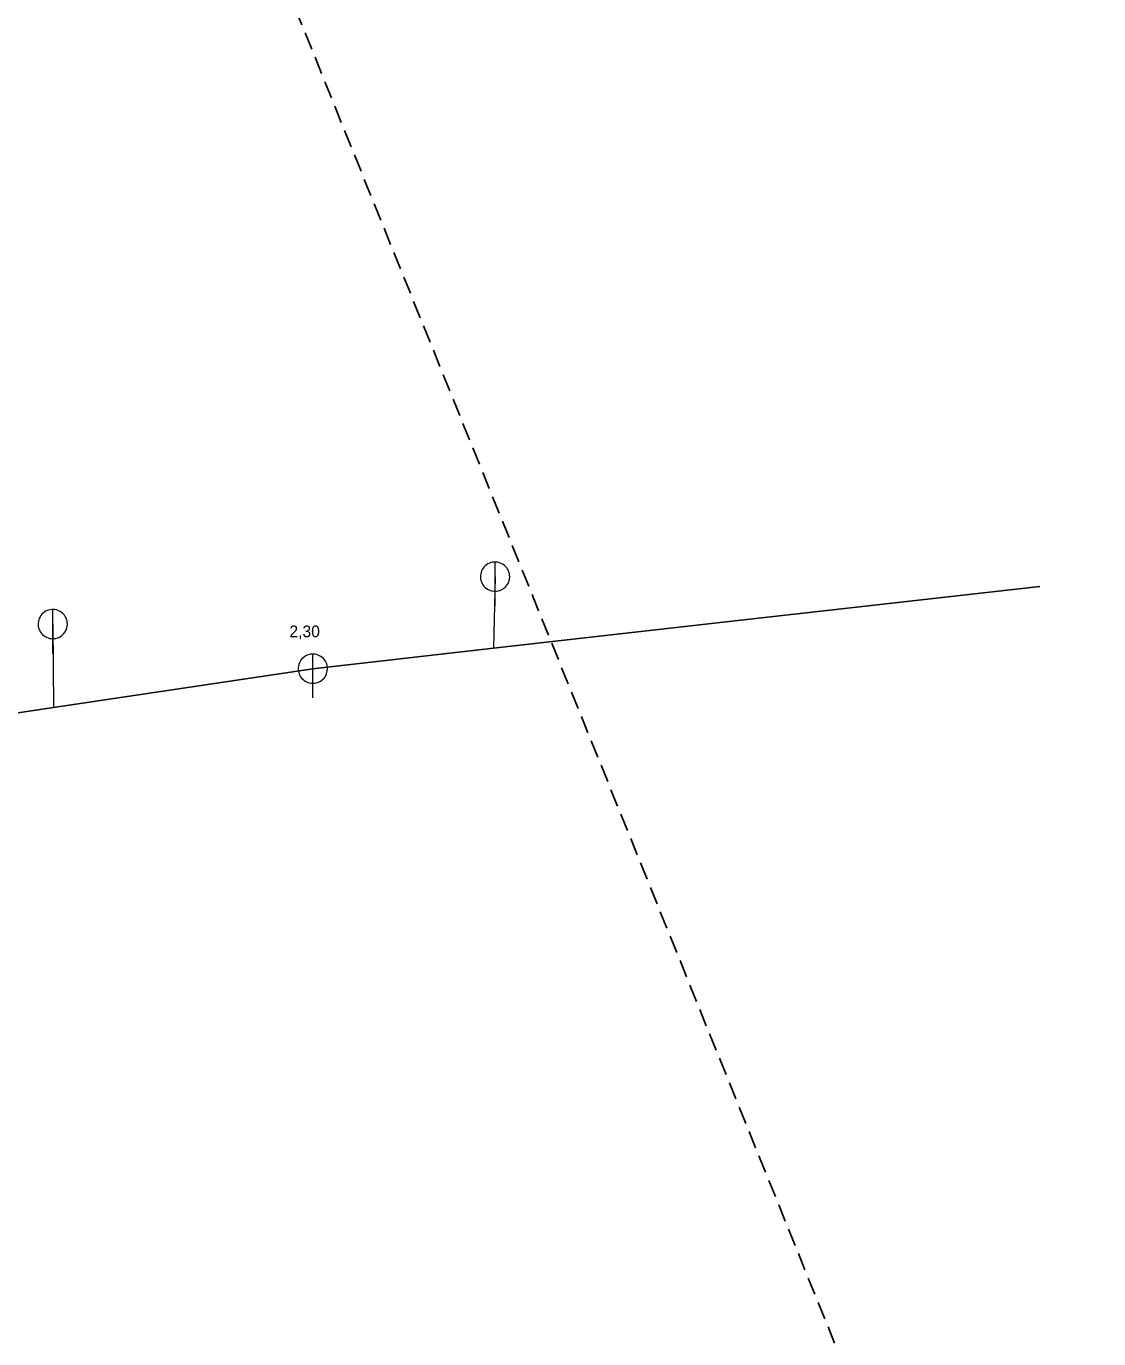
# Model space of a CAD drawing. Extents: x -682839 to -682312, y -994645 to -993949.
# Drawn here: x -682654.5 to -682581.2, y -994218.6 to -994128.9 of the extents above; entities that cross this region are included whole.
import ezdxf

# ---------------------------------------------------------------- set-up
doc = ezdxf.new("R2010")
doc.units = 0
doc.header["$LTSCALE"] = 0.4
doc.linetypes.add('MEDIUM_DASHED', pattern=[4.5, 3, -1.5])
doc.layers.add('1', color=7, linetype='Continuous')
for name, color, linetype, lineweight in [('11', 7, 'Continuous', 13), ('14', 7, 'Continuous', 25), ('22', 7, 'Continuous', 13), ('63', 7, 'MEDIUM_DASHED', 25)]:
    doc.layers.add(name, color=color, linetype=linetype, lineweight=lineweight)

msp = doc.modelspace()

# ---------------------------------------------------------------- linework, layer by layer
at = {"layer": '11'}
for p, q in [((-682622.44, -994166.489), (-682622.539, -994171.379)), ((-682652.66, -994169.73), (-682652.62, -994175.43))]:
    msp.add_line(p, q, dxfattribs=at)
at = {"layer": '14'}
for points in [[(-682585.23, -994167.17), (-682601.59, -994169.01), (-682605.649, -994169.469), (-682622.539, -994171.379), (-682634.89, -994172.78)], [(-682634.89, -994172.78), (-682652.62, -994175.43), (-682674.05, -994178.64), (-682684.149, -994180.09)]]:
    msp.add_lwpolyline(points, dxfattribs=at)
at = {"layer": '22'}
for p, q in [((-682622.44, -994168.489), (-682622.439, -994165.489)), ((-682652.66, -994171.73), (-682652.659, -994168.73)), ((-682634.89, -994174.78), (-682634.889, -994171.78))]:
    msp.add_line(p, q, dxfattribs=at)
for points in [[(-682621.44, -994166.489), (-682621.445, -994166.38), (-682621.463, -994166.272), (-682621.493, -994166.166), (-682621.533, -994166.065), (-682621.585, -994165.968), (-682621.647, -994165.878), (-682621.719, -994165.795), (-682621.799, -994165.721), (-682621.887, -994165.655), (-682621.981, -994165.6), (-682622.081, -994165.555), (-682622.186, -994165.522), (-682622.293, -994165.5), (-682622.402, -994165.49), (-682622.512, -994165.492), (-682622.62, -994165.506), (-682622.727, -994165.531), (-682622.83, -994165.568), (-682622.928, -994165.617), (-682623.02, -994165.675), (-682623.106, -994165.744), (-682623.183, -994165.821), (-682623.252, -994165.907), (-682623.311, -994165.999), (-682623.359, -994166.097), (-682623.396, -994166.2), (-682623.422, -994166.307), (-682623.436, -994166.415), (-682623.439, -994166.525), (-682623.429, -994166.634), (-682623.408, -994166.741), (-682623.374, -994166.845), (-682623.33, -994166.945), (-682623.275, -994167.04), (-682623.209, -994167.128), (-682623.135, -994167.208), (-682623.052, -994167.28), (-682622.962, -994167.342), (-682622.866, -994167.394), (-682622.764, -994167.435), (-682622.659, -994167.465), (-682622.551, -994167.483), (-682622.441, -994167.489), (-682622.332, -994167.483), (-682622.224, -994167.465), (-682622.119, -994167.436), (-682622.017, -994167.395), (-682621.92, -994167.343), (-682621.83, -994167.281), (-682621.747, -994167.21), (-682621.672, -994167.13), (-682621.607, -994167.042), (-682621.551, -994166.948), (-682621.507, -994166.848), (-682621.473, -994166.744), (-682621.451, -994166.636), (-682621.441, -994166.527)], [(-682651.66, -994169.73), (-682651.665, -994169.621), (-682651.683, -994169.513), (-682651.713, -994169.407), (-682651.753, -994169.306), (-682651.805, -994169.209), (-682651.867, -994169.119), (-682651.939, -994169.036), (-682652.019, -994168.962), (-682652.107, -994168.896), (-682652.201, -994168.841), (-682652.301, -994168.796), (-682652.406, -994168.763), (-682652.513, -994168.741), (-682652.622, -994168.731), (-682652.732, -994168.733), (-682652.84, -994168.747), (-682652.947, -994168.772), (-682653.05, -994168.809), (-682653.148, -994168.858), (-682653.24, -994168.916), (-682653.326, -994168.985), (-682653.403, -994169.062), (-682653.472, -994169.148), (-682653.531, -994169.24), (-682653.579, -994169.338), (-682653.616, -994169.441), (-682653.642, -994169.548), (-682653.656, -994169.656), (-682653.659, -994169.766), (-682653.649, -994169.875), (-682653.628, -994169.982), (-682653.594, -994170.086), (-682653.55, -994170.186), (-682653.495, -994170.281), (-682653.429, -994170.369), (-682653.355, -994170.449), (-682653.272, -994170.521), (-682653.182, -994170.583), (-682653.086, -994170.635), (-682652.984, -994170.676), (-682652.879, -994170.706), (-682652.771, -994170.724), (-682652.661, -994170.73), (-682652.552, -994170.724), (-682652.444, -994170.706), (-682652.339, -994170.677), (-682652.237, -994170.636), (-682652.14, -994170.584), (-682652.05, -994170.522), (-682651.967, -994170.451), (-682651.892, -994170.371), (-682651.827, -994170.283), (-682651.771, -994170.189), (-682651.727, -994170.089), (-682651.693, -994169.985), (-682651.671, -994169.877), (-682651.661, -994169.768)], [(-682633.89, -994172.78), (-682633.895, -994172.671), (-682633.913, -994172.563), (-682633.943, -994172.457), (-682633.983, -994172.356), (-682634.035, -994172.259), (-682634.097, -994172.169), (-682634.169, -994172.086), (-682634.249, -994172.012), (-682634.337, -994171.946), (-682634.431, -994171.891), (-682634.531, -994171.846), (-682634.636, -994171.813), (-682634.743, -994171.791), (-682634.852, -994171.781), (-682634.962, -994171.783), (-682635.07, -994171.797), (-682635.177, -994171.822), (-682635.28, -994171.859), (-682635.378, -994171.908), (-682635.47, -994171.966), (-682635.556, -994172.035), (-682635.633, -994172.112), (-682635.702, -994172.198), (-682635.761, -994172.29), (-682635.809, -994172.388), (-682635.846, -994172.491), (-682635.872, -994172.598), (-682635.886, -994172.706), (-682635.889, -994172.816), (-682635.879, -994172.925), (-682635.858, -994173.032), (-682635.824, -994173.136), (-682635.78, -994173.236), (-682635.725, -994173.331), (-682635.659, -994173.419), (-682635.585, -994173.499), (-682635.502, -994173.571), (-682635.412, -994173.633), (-682635.316, -994173.685), (-682635.214, -994173.726), (-682635.109, -994173.756), (-682635.001, -994173.774), (-682634.891, -994173.78), (-682634.782, -994173.774), (-682634.674, -994173.756), (-682634.569, -994173.727), (-682634.467, -994173.686), (-682634.37, -994173.634), (-682634.28, -994173.572), (-682634.197, -994173.501), (-682634.122, -994173.421), (-682634.057, -994173.333), (-682634.001, -994173.239), (-682633.957, -994173.139), (-682633.923, -994173.035), (-682633.901, -994172.927), (-682633.891, -994172.818)]]:
    msp.add_lwpolyline(points, close=True, dxfattribs=at)
at = {"layer": '63'}
msp.add_lwpolyline([(-682494.62, -994477.955), (-682564.4, -994570.065), (-682564.4, -994570.065), (-682684.423, -994544.944), (-682684.423, -994544.944), (-682751.412, -994042.525), (-682751.412, -994042.525), (-682670.466, -994042.525), (-682670.466, -994042.525)], close=True, dxfattribs=at)

# ---------------------------------------------------------------- texts
at = {"layer": '1'}
msp.add_text('2,30', height=0.8, dxfattribs=at).set_placement((-682636.49, -994170.627))

doc.saveas('drawing.dxf')
